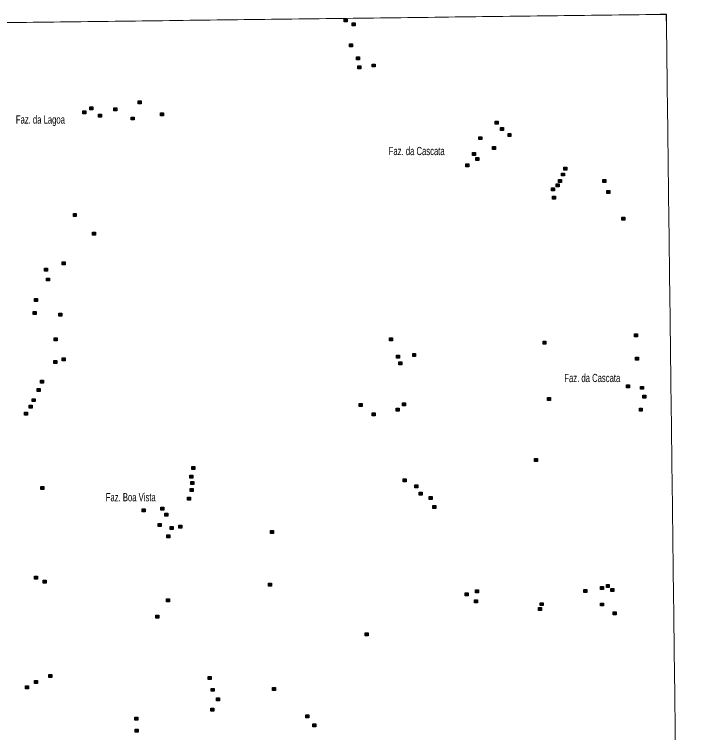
# Model space of a CAD drawing. Extents: x 265.7 to 292.1, y 7676.2 to 7704.2.
# Drawn here: x 285.4 to 292.1, y 7697.19 to 7704.2 of the extents above; entities that cross this region are included whole.
import ezdxf

# ---------------------------------------------------------------- set-up
doc = ezdxf.new("R2010")
doc.units = 0
doc.header["$LTSCALE"] = 0.032
doc.layers.add('2', color=7, linetype='Continuous', lineweight=25)
doc.layers.add('63', color=7, linetype='Continuous', lineweight=13)
doc.layers.add('61', color=7, linetype='Continuous')

msp = doc.modelspace()

# ---------------------------------------------------------------- hatches: boundary and pattern name
at = {"layer": '2'}
for points in [[(288.614, 7704.1576), (288.643, 7704.1576), (288.643, 7704.1286), (288.614, 7704.1286)], [(288.6907, 7704.1205), (288.7197, 7704.1205), (288.7197, 7704.0915), (288.6907, 7704.0915)], [(288.6656, 7703.9147), (288.6946, 7703.9147), (288.6946, 7703.8857), (288.6656, 7703.8857)], [(288.7334, 7703.7896), (288.7624, 7703.7896), (288.7624, 7703.7606), (288.7334, 7703.7606)], [(288.8868, 7703.7186), (288.9158, 7703.7186), (288.9158, 7703.6896), (288.8868, 7703.6896)], [(288.7478, 7703.6991), (288.7768, 7703.6991), (288.7768, 7703.6701), (288.7478, 7703.6701)], [(286.6037, 7703.3586), (286.6327, 7703.3586), (286.6327, 7703.3296), (286.6037, 7703.3296)], [(286.1315, 7703.2998), (286.1605, 7703.2998), (286.1605, 7703.2708), (286.1315, 7703.2708)], [(286.3647, 7703.2899), (286.3937, 7703.2899), (286.3937, 7703.2609), (286.3647, 7703.2609)], [(286.062, 7703.2617), (286.091, 7703.2617), (286.091, 7703.2327), (286.062, 7703.2327)], [(286.2178, 7703.2295), (286.2468, 7703.2295), (286.2468, 7703.2005), (286.2178, 7703.2005)], [(286.8207, 7703.2408), (286.8497, 7703.2408), (286.8497, 7703.2118), (286.8207, 7703.2118)], [(286.5342, 7703.2012), (286.5632, 7703.2012), (286.5632, 7703.1722), (286.5342, 7703.1722)], [(290.0861, 7703.16), (290.1151, 7703.16), (290.1151, 7703.131), (290.0861, 7703.131)], [(290.1385, 7703.0987), (290.1675, 7703.0987), (290.1675, 7703.0697), (290.1385, 7703.0697)], [(289.927, 7703.0092), (289.956, 7703.0092), (289.956, 7702.9802), (289.927, 7702.9802)], [(290.2127, 7703.0415), (290.2417, 7703.0415), (290.2417, 7703.0125), (290.2127, 7703.0125)], [(290.061, 7702.9131), (290.09, 7702.9131), (290.09, 7702.8841), (290.061, 7702.8841)], [(289.8657, 7702.855), (289.8947, 7702.855), (289.8947, 7702.826), (289.8657, 7702.826)], [(289.8997, 7702.8066), (289.9287, 7702.8066), (289.9287, 7702.7776), (289.8997, 7702.7776)], [(289.8018, 7702.7436), (289.8308, 7702.7436), (289.8308, 7702.7146), (289.8018, 7702.7146)], [(290.7357, 7702.6548), (290.7647, 7702.6548), (290.7647, 7702.6258), (290.7357, 7702.6258)], [(290.7563, 7702.7108), (290.7853, 7702.7108), (290.7853, 7702.6818), (290.7563, 7702.6818)], [(290.705, 7702.5919), (290.734, 7702.5919), (290.734, 7702.5629), (290.705, 7702.5629)], [(291.1393, 7702.5903), (291.1683, 7702.5903), (291.1683, 7702.5613), (291.1393, 7702.5613)], [(290.6364, 7702.5104), (290.6654, 7702.5104), (290.6654, 7702.4814), (290.6364, 7702.4814)], [(290.6825, 7702.5484), (290.7115, 7702.5484), (290.7115, 7702.5194), (290.6825, 7702.5194)], [(291.178, 7702.4838), (291.207, 7702.4838), (291.207, 7702.4548), (291.178, 7702.4548)], [(290.647, 7702.429), (290.676, 7702.429), (290.676, 7702.4), (290.647, 7702.4)], [(285.9709, 7702.2586), (285.9999, 7702.2586), (285.9999, 7702.2296), (285.9709, 7702.2296)], [(291.324, 7702.2223), (291.353, 7702.2223), (291.353, 7702.1933), (291.324, 7702.1933)], [(286.1565, 7702.0786), (286.1855, 7702.0786), (286.1855, 7702.0496), (286.1565, 7702.0496)], [(285.8612, 7701.7865), (285.8902, 7701.7865), (285.8902, 7701.7575), (285.8612, 7701.7575)], [(285.6884, 7701.7251), (285.7174, 7701.7251), (285.7174, 7701.6961), (285.6884, 7701.6961)], [(285.7101, 7701.6299), (285.7391, 7701.6299), (285.7391, 7701.6009), (285.7101, 7701.6009)], [(285.5932, 7701.4307), (285.6222, 7701.4307), (285.6222, 7701.4017), (285.5932, 7701.4017)], [(285.5796, 7701.3039), (285.6086, 7701.3039), (285.6086, 7701.2749), (285.5796, 7701.2749)], [(285.8295, 7701.2877), (285.8585, 7701.2877), (285.8585, 7701.2587), (285.8295, 7701.2587)], [(285.7837, 7701.0457), (285.8127, 7701.0457), (285.8127, 7701.0167), (285.7837, 7701.0167)], [(289.0554, 7701.0456), (289.0844, 7701.0456), (289.0844, 7701.0166), (289.0554, 7701.0166)], [(291.4467, 7701.0851), (291.4757, 7701.0851), (291.4757, 7701.0561), (291.4467, 7701.0561)], [(290.5541, 7701.0134), (290.5831, 7701.0134), (290.5831, 7700.9844), (290.5541, 7700.9844)], [(285.8612, 7700.8494), (285.8902, 7700.8494), (285.8902, 7700.8204), (285.8612, 7700.8204)], [(289.1231, 7700.8754), (289.1521, 7700.8754), (289.1521, 7700.8464), (289.1231, 7700.8464)], [(289.2824, 7700.893), (289.3114, 7700.893), (289.3114, 7700.864), (289.2824, 7700.864)], [(291.4564, 7700.8576), (291.4854, 7700.8576), (291.4854, 7700.8286), (291.4564, 7700.8286)], [(285.7803, 7700.8236), (285.8093, 7700.8236), (285.8093, 7700.7946), (285.7803, 7700.7946)], [(289.1459, 7700.8107), (289.1749, 7700.8107), (289.1749, 7700.7817), (289.1459, 7700.7817)], [(285.6497, 7700.6341), (285.6787, 7700.6341), (285.6787, 7700.6051), (285.6497, 7700.6051)], [(285.6174, 7700.5517), (285.6464, 7700.5517), (285.6464, 7700.5227), (285.6174, 7700.5227)], [(291.3685, 7700.5872), (291.3975, 7700.5872), (291.3975, 7700.5582), (291.3685, 7700.5582)], [(291.5064, 7700.5727), (291.5354, 7700.5727), (291.5354, 7700.5437), (291.5064, 7700.5437)], [(291.529, 7700.4871), (291.558, 7700.4871), (291.558, 7700.4581), (291.529, 7700.4581)], [(285.5697, 7700.4524), (285.5987, 7700.4524), (285.5987, 7700.4234), (285.5697, 7700.4234)], [(288.7593, 7700.4065), (288.7883, 7700.4065), (288.7883, 7700.3775), (288.7593, 7700.3775)], [(289.1822, 7700.412), (289.2112, 7700.412), (289.2112, 7700.383), (289.1822, 7700.383)], [(290.5993, 7700.463), (290.6283, 7700.463), (290.6283, 7700.434), (290.5993, 7700.434)], [(285.5391, 7700.388), (285.5681, 7700.388), (285.5681, 7700.359), (285.5391, 7700.359)], [(289.1216, 7700.3589), (289.1506, 7700.3589), (289.1506, 7700.3299), (289.1216, 7700.3299)], [(291.4944, 7700.3596), (291.5234, 7700.3596), (291.5234, 7700.3306), (291.4944, 7700.3306)], [(285.4939, 7700.32), (285.5229, 7700.32), (285.5229, 7700.291), (285.4939, 7700.291)], [(288.8876, 7700.3127), (288.9166, 7700.3127), (288.9166, 7700.2837), (288.8876, 7700.2837)], [(290.4718, 7699.8674), (290.5008, 7699.8674), (290.5008, 7699.8384), (290.4718, 7699.8384)], [(287.1266, 7699.7907), (287.1556, 7699.7907), (287.1556, 7699.7617), (287.1266, 7699.7617)], [(287.1088, 7699.7067), (287.1378, 7699.7067), (287.1378, 7699.6777), (287.1088, 7699.6777)], [(287.1168, 7699.6446), (287.1458, 7699.6446), (287.1458, 7699.6156), (287.1168, 7699.6156)], [(289.1894, 7699.6687), (289.2184, 7699.6687), (289.2184, 7699.6397), (289.1894, 7699.6397)], [(285.6529, 7699.5962), (285.6819, 7699.5962), (285.6819, 7699.5672), (285.6529, 7699.5672)], [(287.1113, 7699.5751), (287.1403, 7699.5751), (287.1403, 7699.5461), (287.1113, 7699.5461)], [(289.304, 7699.6107), (289.333, 7699.6107), (289.333, 7699.5817), (289.304, 7699.5817)], [(289.346, 7699.5413), (289.375, 7699.5413), (289.375, 7699.5123), (289.346, 7699.5123)], [(289.442, 7699.4976), (289.471, 7699.4976), (289.471, 7699.4686), (289.442, 7699.4686)], [(287.0845, 7699.4921), (287.1135, 7699.4921), (287.1135, 7699.4631), (287.0845, 7699.4631)], [(286.644, 7699.3783), (286.673, 7699.3783), (286.673, 7699.3493), (286.644, 7699.3493)], [(286.8256, 7699.3936), (286.8546, 7699.3936), (286.8546, 7699.3646), (286.8256, 7699.3646)], [(289.4791, 7699.4089), (289.5081, 7699.4089), (289.5081, 7699.3799), (289.4791, 7699.3799)], [(286.8643, 7699.3347), (286.8933, 7699.3347), (286.8933, 7699.3057), (286.8643, 7699.3057)], [(286.7989, 7699.2345), (286.8279, 7699.2345), (286.8279, 7699.2055), (286.7989, 7699.2055)], [(287.0006, 7699.2185), (287.0296, 7699.2185), (287.0296, 7699.1895), (287.0006, 7699.1895)], [(286.9167, 7699.204), (286.9457, 7699.204), (286.9457, 7699.175), (286.9167, 7699.175)], [(287.8964, 7699.166), (287.9254, 7699.166), (287.9254, 7699.137), (287.8964, 7699.137)], [(286.8828, 7699.1232), (286.9118, 7699.1232), (286.9118, 7699.0942), (286.8828, 7699.0942)], [(285.5924, 7698.7197), (285.6214, 7698.7197), (285.6214, 7698.6907), (285.5924, 7698.6907)], [(285.6763, 7698.6801), (285.7053, 7698.6801), (285.7053, 7698.6511), (285.6763, 7698.6511)], [(287.8764, 7698.6511), (287.9054, 7698.6511), (287.9054, 7698.6221), (287.8764, 7698.6221)], [(289.8948, 7698.5857), (289.9238, 7698.5857), (289.9238, 7698.5567), (289.8948, 7698.5567)], [(290.9536, 7698.5897), (290.9826, 7698.5897), (290.9826, 7698.5607), (290.9536, 7698.5607)], [(291.115, 7698.6187), (291.144, 7698.6187), (291.144, 7698.5897), (291.115, 7698.5897)], [(291.1723, 7698.639), (291.2013, 7698.639), (291.2013, 7698.61), (291.1723, 7698.61)], [(291.2168, 7698.5995), (291.2458, 7698.5995), (291.2458, 7698.5705), (291.2168, 7698.5705)], [(289.7947, 7698.5582), (289.8237, 7698.5582), (289.8237, 7698.5292), (289.7947, 7698.5292)], [(286.8812, 7698.4986), (286.9102, 7698.4986), (286.9102, 7698.4696), (286.8812, 7698.4696)], [(289.885, 7698.4889), (289.914, 7698.4889), (289.914, 7698.4599), (289.885, 7698.4599)], [(290.5275, 7698.4614), (290.5565, 7698.4614), (290.5565, 7698.4324), (290.5275, 7698.4324)], [(291.115, 7698.4582), (291.144, 7698.4582), (291.144, 7698.4292), (291.115, 7698.4292)], [(290.5098, 7698.4139), (290.5388, 7698.4139), (290.5388, 7698.3849), (290.5098, 7698.3849)], [(286.7755, 7698.3388), (286.8045, 7698.3388), (286.8045, 7698.3098), (286.7755, 7698.3098)], [(291.2401, 7698.3711), (291.2691, 7698.3711), (291.2691, 7698.3421), (291.2401, 7698.3421)], [(288.8173, 7698.1684), (288.8463, 7698.1684), (288.8463, 7698.1394), (288.8173, 7698.1394)], [(285.7321, 7697.7609), (285.7611, 7697.7609), (285.7611, 7697.7319), (285.7321, 7697.7319)], [(285.5931, 7697.7013), (285.6221, 7697.7013), (285.6221, 7697.6723), (285.5931, 7697.6723)], [(287.2856, 7697.7415), (287.3146, 7697.7415), (287.3146, 7697.7125), (287.2856, 7697.7125)], [(285.5044, 7697.6496), (285.5334, 7697.6496), (285.5334, 7697.6206), (285.5044, 7697.6206)], [(287.3146, 7697.6254), (287.3436, 7697.6254), (287.3436, 7697.5964), (287.3146, 7697.5964)], [(287.9158, 7697.635), (287.9448, 7697.635), (287.9448, 7697.606), (287.9158, 7697.606)], [(287.3678, 7697.5317), (287.3968, 7697.5317), (287.3968, 7697.5027), (287.3678, 7697.5027)], [(287.3139, 7697.4333), (287.3429, 7697.4333), (287.3429, 7697.4043), (287.3139, 7697.4043)], [(286.5706, 7697.3429), (286.5996, 7697.3429), (286.5996, 7697.3139), (286.5706, 7697.3139)], [(288.2411, 7697.3679), (288.2701, 7697.3679), (288.2701, 7697.3389), (288.2411, 7697.3389)], [(288.3073, 7697.2783), (288.3363, 7697.2783), (288.3363, 7697.2493), (288.3073, 7697.2493)], [(286.5737, 7697.2267), (286.6027, 7697.2267), (286.6027, 7697.1977), (286.5737, 7697.1977)]]:
    msp.add_hatch(color=256, dxfattribs=at).paths.add_polyline_path(points)

# ---------------------------------------------------------------- linework, layer by layer
for points in [[(288.614, 7704.1576), (288.643, 7704.1576), (288.643, 7704.1286), (288.614, 7704.1286)], [(288.6907, 7704.1205), (288.7197, 7704.1205), (288.7197, 7704.0915), (288.6907, 7704.0915)], [(288.6656, 7703.9147), (288.6946, 7703.9147), (288.6946, 7703.8857), (288.6656, 7703.8857)], [(288.7334, 7703.7896), (288.7624, 7703.7896), (288.7624, 7703.7606), (288.7334, 7703.7606)], [(288.8868, 7703.7186), (288.9158, 7703.7186), (288.9158, 7703.6896), (288.8868, 7703.6896)], [(288.7478, 7703.6991), (288.7768, 7703.6991), (288.7768, 7703.6701), (288.7478, 7703.6701)], [(286.6037, 7703.3586), (286.6327, 7703.3586), (286.6327, 7703.3296), (286.6037, 7703.3296)], [(286.1315, 7703.2998), (286.1605, 7703.2998), (286.1605, 7703.2708), (286.1315, 7703.2708)], [(286.3647, 7703.2899), (286.3937, 7703.2899), (286.3937, 7703.2609), (286.3647, 7703.2609)], [(286.062, 7703.2617), (286.091, 7703.2617), (286.091, 7703.2327), (286.062, 7703.2327)], [(286.2178, 7703.2295), (286.2468, 7703.2295), (286.2468, 7703.2005), (286.2178, 7703.2005)], [(286.8207, 7703.2408), (286.8497, 7703.2408), (286.8497, 7703.2118), (286.8207, 7703.2118)], [(286.5342, 7703.2012), (286.5632, 7703.2012), (286.5632, 7703.1722), (286.5342, 7703.1722)], [(290.0861, 7703.16), (290.1151, 7703.16), (290.1151, 7703.131), (290.0861, 7703.131)], [(290.1385, 7703.0987), (290.1675, 7703.0987), (290.1675, 7703.0697), (290.1385, 7703.0697)], [(289.927, 7703.0092), (289.956, 7703.0092), (289.956, 7702.9802), (289.927, 7702.9802)], [(290.2127, 7703.0415), (290.2417, 7703.0415), (290.2417, 7703.0125), (290.2127, 7703.0125)], [(290.061, 7702.9131), (290.09, 7702.9131), (290.09, 7702.8841), (290.061, 7702.8841)], [(289.8657, 7702.855), (289.8947, 7702.855), (289.8947, 7702.826), (289.8657, 7702.826)], [(289.8997, 7702.8066), (289.9287, 7702.8066), (289.9287, 7702.7776), (289.8997, 7702.7776)], [(289.8018, 7702.7436), (289.8308, 7702.7436), (289.8308, 7702.7146), (289.8018, 7702.7146)], [(290.7357, 7702.6548), (290.7647, 7702.6548), (290.7647, 7702.6258), (290.7357, 7702.6258)], [(290.7563, 7702.7108), (290.7853, 7702.7108), (290.7853, 7702.6818), (290.7563, 7702.6818)], [(290.705, 7702.5919), (290.734, 7702.5919), (290.734, 7702.5629), (290.705, 7702.5629)], [(291.1393, 7702.5903), (291.1683, 7702.5903), (291.1683, 7702.5613), (291.1393, 7702.5613)], [(290.6364, 7702.5104), (290.6654, 7702.5104), (290.6654, 7702.4814), (290.6364, 7702.4814)], [(290.6825, 7702.5484), (290.7115, 7702.5484), (290.7115, 7702.5194), (290.6825, 7702.5194)], [(291.178, 7702.4838), (291.207, 7702.4838), (291.207, 7702.4548), (291.178, 7702.4548)], [(290.647, 7702.429), (290.676, 7702.429), (290.676, 7702.4), (290.647, 7702.4)], [(285.9709, 7702.2586), (285.9999, 7702.2586), (285.9999, 7702.2296), (285.9709, 7702.2296)], [(291.324, 7702.2223), (291.353, 7702.2223), (291.353, 7702.1933), (291.324, 7702.1933)], [(286.1565, 7702.0786), (286.1855, 7702.0786), (286.1855, 7702.0496), (286.1565, 7702.0496)], [(285.8612, 7701.7865), (285.8902, 7701.7865), (285.8902, 7701.7575), (285.8612, 7701.7575)], [(285.6884, 7701.7251), (285.7174, 7701.7251), (285.7174, 7701.6961), (285.6884, 7701.6961)], [(285.7101, 7701.6299), (285.7391, 7701.6299), (285.7391, 7701.6009), (285.7101, 7701.6009)], [(285.5932, 7701.4307), (285.6222, 7701.4307), (285.6222, 7701.4017), (285.5932, 7701.4017)], [(285.5796, 7701.3039), (285.6086, 7701.3039), (285.6086, 7701.2749), (285.5796, 7701.2749)], [(285.8295, 7701.2877), (285.8585, 7701.2877), (285.8585, 7701.2587), (285.8295, 7701.2587)], [(285.7837, 7701.0457), (285.8127, 7701.0457), (285.8127, 7701.0167), (285.7837, 7701.0167)], [(289.0554, 7701.0456), (289.0844, 7701.0456), (289.0844, 7701.0166), (289.0554, 7701.0166)], [(291.4467, 7701.0851), (291.4757, 7701.0851), (291.4757, 7701.0561), (291.4467, 7701.0561)], [(290.5541, 7701.0134), (290.5831, 7701.0134), (290.5831, 7700.9844), (290.5541, 7700.9844)], [(285.8612, 7700.8494), (285.8902, 7700.8494), (285.8902, 7700.8204), (285.8612, 7700.8204)], [(289.1231, 7700.8754), (289.1521, 7700.8754), (289.1521, 7700.8464), (289.1231, 7700.8464)], [(289.2824, 7700.893), (289.3114, 7700.893), (289.3114, 7700.864), (289.2824, 7700.864)], [(291.4564, 7700.8576), (291.4854, 7700.8576), (291.4854, 7700.8286), (291.4564, 7700.8286)], [(285.7803, 7700.8236), (285.8093, 7700.8236), (285.8093, 7700.7946), (285.7803, 7700.7946)], [(289.1459, 7700.8107), (289.1749, 7700.8107), (289.1749, 7700.7817), (289.1459, 7700.7817)], [(285.6497, 7700.6341), (285.6787, 7700.6341), (285.6787, 7700.6051), (285.6497, 7700.6051)], [(285.6174, 7700.5517), (285.6464, 7700.5517), (285.6464, 7700.5227), (285.6174, 7700.5227)], [(291.3685, 7700.5872), (291.3975, 7700.5872), (291.3975, 7700.5582), (291.3685, 7700.5582)], [(291.5064, 7700.5727), (291.5354, 7700.5727), (291.5354, 7700.5437), (291.5064, 7700.5437)], [(291.529, 7700.4871), (291.558, 7700.4871), (291.558, 7700.4581), (291.529, 7700.4581)], [(285.5697, 7700.4524), (285.5987, 7700.4524), (285.5987, 7700.4234), (285.5697, 7700.4234)], [(288.7593, 7700.4065), (288.7883, 7700.4065), (288.7883, 7700.3775), (288.7593, 7700.3775)], [(289.1822, 7700.412), (289.2112, 7700.412), (289.2112, 7700.383), (289.1822, 7700.383)], [(290.5993, 7700.463), (290.6283, 7700.463), (290.6283, 7700.434), (290.5993, 7700.434)], [(285.5391, 7700.388), (285.5681, 7700.388), (285.5681, 7700.359), (285.5391, 7700.359)], [(289.1216, 7700.3589), (289.1506, 7700.3589), (289.1506, 7700.3299), (289.1216, 7700.3299)], [(291.4944, 7700.3596), (291.5234, 7700.3596), (291.5234, 7700.3306), (291.4944, 7700.3306)], [(285.4939, 7700.32), (285.5229, 7700.32), (285.5229, 7700.291), (285.4939, 7700.291)], [(288.8876, 7700.3127), (288.9166, 7700.3127), (288.9166, 7700.2837), (288.8876, 7700.2837)], [(290.4718, 7699.8674), (290.5008, 7699.8674), (290.5008, 7699.8384), (290.4718, 7699.8384)], [(287.1266, 7699.7907), (287.1556, 7699.7907), (287.1556, 7699.7617), (287.1266, 7699.7617)], [(287.1088, 7699.7067), (287.1378, 7699.7067), (287.1378, 7699.6777), (287.1088, 7699.6777)], [(287.1168, 7699.6446), (287.1458, 7699.6446), (287.1458, 7699.6156), (287.1168, 7699.6156)], [(289.1894, 7699.6687), (289.2184, 7699.6687), (289.2184, 7699.6397), (289.1894, 7699.6397)], [(285.6529, 7699.5962), (285.6819, 7699.5962), (285.6819, 7699.5672), (285.6529, 7699.5672)], [(287.1113, 7699.5751), (287.1403, 7699.5751), (287.1403, 7699.5461), (287.1113, 7699.5461)], [(289.304, 7699.6107), (289.333, 7699.6107), (289.333, 7699.5817), (289.304, 7699.5817)], [(289.346, 7699.5413), (289.375, 7699.5413), (289.375, 7699.5123), (289.346, 7699.5123)], [(289.442, 7699.4976), (289.471, 7699.4976), (289.471, 7699.4686), (289.442, 7699.4686)], [(287.0845, 7699.4921), (287.1135, 7699.4921), (287.1135, 7699.4631), (287.0845, 7699.4631)], [(286.644, 7699.3783), (286.673, 7699.3783), (286.673, 7699.3493), (286.644, 7699.3493)], [(286.8256, 7699.3936), (286.8546, 7699.3936), (286.8546, 7699.3646), (286.8256, 7699.3646)], [(289.4791, 7699.4089), (289.5081, 7699.4089), (289.5081, 7699.3799), (289.4791, 7699.3799)], [(286.8643, 7699.3347), (286.8933, 7699.3347), (286.8933, 7699.3057), (286.8643, 7699.3057)], [(286.7989, 7699.2345), (286.8279, 7699.2345), (286.8279, 7699.2055), (286.7989, 7699.2055)], [(287.0006, 7699.2185), (287.0296, 7699.2185), (287.0296, 7699.1895), (287.0006, 7699.1895)], [(286.9167, 7699.204), (286.9457, 7699.204), (286.9457, 7699.175), (286.9167, 7699.175)], [(287.8964, 7699.166), (287.9254, 7699.166), (287.9254, 7699.137), (287.8964, 7699.137)], [(286.8828, 7699.1232), (286.9118, 7699.1232), (286.9118, 7699.0942), (286.8828, 7699.0942)], [(285.5924, 7698.7197), (285.6214, 7698.7197), (285.6214, 7698.6907), (285.5924, 7698.6907)], [(285.6763, 7698.6801), (285.7053, 7698.6801), (285.7053, 7698.6511), (285.6763, 7698.6511)], [(287.8764, 7698.6511), (287.9054, 7698.6511), (287.9054, 7698.6221), (287.8764, 7698.6221)], [(289.8948, 7698.5857), (289.9238, 7698.5857), (289.9238, 7698.5567), (289.8948, 7698.5567)], [(290.9536, 7698.5897), (290.9826, 7698.5897), (290.9826, 7698.5607), (290.9536, 7698.5607)], [(291.115, 7698.6187), (291.144, 7698.6187), (291.144, 7698.5897), (291.115, 7698.5897)], [(291.1723, 7698.639), (291.2013, 7698.639), (291.2013, 7698.61), (291.1723, 7698.61)], [(291.2168, 7698.5995), (291.2458, 7698.5995), (291.2458, 7698.5705), (291.2168, 7698.5705)], [(289.7947, 7698.5582), (289.8237, 7698.5582), (289.8237, 7698.5292), (289.7947, 7698.5292)], [(286.8812, 7698.4986), (286.9102, 7698.4986), (286.9102, 7698.4696), (286.8812, 7698.4696)], [(289.885, 7698.4889), (289.914, 7698.4889), (289.914, 7698.4599), (289.885, 7698.4599)], [(290.5275, 7698.4614), (290.5565, 7698.4614), (290.5565, 7698.4324), (290.5275, 7698.4324)], [(291.115, 7698.4582), (291.144, 7698.4582), (291.144, 7698.4292), (291.115, 7698.4292)], [(290.5098, 7698.4139), (290.5388, 7698.4139), (290.5388, 7698.3849), (290.5098, 7698.3849)], [(286.7755, 7698.3388), (286.8045, 7698.3388), (286.8045, 7698.3098), (286.7755, 7698.3098)], [(291.2401, 7698.3711), (291.2691, 7698.3711), (291.2691, 7698.3421), (291.2401, 7698.3421)], [(288.8173, 7698.1684), (288.8463, 7698.1684), (288.8463, 7698.1394), (288.8173, 7698.1394)], [(285.7321, 7697.7609), (285.7611, 7697.7609), (285.7611, 7697.7319), (285.7321, 7697.7319)], [(285.5931, 7697.7013), (285.6221, 7697.7013), (285.6221, 7697.6723), (285.5931, 7697.6723)], [(287.2856, 7697.7415), (287.3146, 7697.7415), (287.3146, 7697.7125), (287.2856, 7697.7125)], [(285.5044, 7697.6496), (285.5334, 7697.6496), (285.5334, 7697.6206), (285.5044, 7697.6206)], [(287.3146, 7697.6254), (287.3436, 7697.6254), (287.3436, 7697.5964), (287.3146, 7697.5964)], [(287.9158, 7697.635), (287.9448, 7697.635), (287.9448, 7697.606), (287.9158, 7697.606)], [(287.3678, 7697.5317), (287.3968, 7697.5317), (287.3968, 7697.5027), (287.3678, 7697.5027)], [(287.3139, 7697.4333), (287.3429, 7697.4333), (287.3429, 7697.4043), (287.3139, 7697.4043)], [(286.5706, 7697.3429), (286.5996, 7697.3429), (286.5996, 7697.3139), (286.5706, 7697.3139)], [(288.2411, 7697.3679), (288.2701, 7697.3679), (288.2701, 7697.3389), (288.2411, 7697.3389)], [(288.3073, 7697.2783), (288.3363, 7697.2783), (288.3363, 7697.2493), (288.3073, 7697.2493)], [(286.5737, 7697.2267), (286.6027, 7697.2267), (286.6027, 7697.1977), (286.5737, 7697.1977)]]:
    msp.add_lwpolyline(points, close=True, dxfattribs=at)
at = {"layer": '63', "lineweight": 25}
msp.add_lwpolyline([(291.7584, 7704.1407), (291.7584, 7704.2023), (291.6977, 7704.2023)], dxfattribs=at)
at = {"layer": '63'}
for points in [[(265.7179, 7703.8606), (266.2494, 7703.868), (266.7808, 7703.8754), (267.3123, 7703.8828), (267.8437, 7703.8901), (268.3752, 7703.8974), (268.9066, 7703.9047), (269.4381, 7703.912), (269.9695, 7703.9193), (270.501, 7703.9265), (271.0324, 7703.9338), (271.5639, 7703.941), (272.0953, 7703.9482), (272.6268, 7703.9554), (273.1582, 7703.9626), (273.6896, 7703.9697), (274.2211, 7703.9769), (274.7525, 7703.984), (275.2839, 7703.9911), (275.8154, 7703.9982), (276.3468, 7704.0052), (276.8782, 7704.0123), (277.4097, 7704.0193), (277.9411, 7704.0263), (278.4725, 7704.0333), (279.0039, 7704.0403), (279.5354, 7704.0473), (280.0668, 7704.0543), (280.5982, 7704.0612), (281.1296, 7704.0681), (281.661, 7704.075), (282.1925, 7704.0819), (282.7239, 7704.0888), (283.2553, 7704.0956), (283.7867, 7704.1025), (284.3181, 7704.1093), (284.8495, 7704.1161), (285.3809, 7704.1229), (285.9123, 7704.1296), (286.4437, 7704.1364), (286.9751, 7704.1431), (287.5065, 7704.1498), (288.0379, 7704.1565), (288.5693, 7704.1632), (289.1007, 7704.1699), (289.6321, 7704.1765), (290.1635, 7704.1832), (290.6949, 7704.1898), (291.2263, 7704.1964), (291.7577, 7704.203)], [(292.1022, 7676.5221), (292.0951, 7677.087), (292.088, 7677.6519), (292.081, 7678.2168), (292.0739, 7678.7818), (292.0668, 7679.3467), (292.0598, 7679.9116), (292.0527, 7680.4765), (292.0457, 7681.0414), (292.0386, 7681.6064), (292.0316, 7682.1713), (292.0245, 7682.7362), (292.0175, 7683.3011), (292.0104, 7683.866), (292.0034, 7684.431), (291.9963, 7684.9959), (291.9893, 7685.5608), (291.9822, 7686.1257), (291.9752, 7686.6906), (291.9681, 7687.2556), (291.9611, 7687.8205), (291.9541, 7688.3854), (291.947, 7688.9503), (291.94, 7689.5152), (291.933, 7690.0801), (291.9259, 7690.6451), (291.9189, 7691.21), (291.9119, 7691.7749), (291.9049, 7692.3398), (291.8978, 7692.9047), (291.8908, 7693.4696), (291.8838, 7694.0345), (291.8768, 7694.5995), (291.8698, 7695.1644), (291.8628, 7695.7293), (291.8557, 7696.2942), (291.8487, 7696.8591), (291.8417, 7697.424), (291.8347, 7697.9889), (291.8277, 7698.5539), (291.8207, 7699.1188), (291.8137, 7699.6837), (291.8067, 7700.2486), (291.7997, 7700.8135), (291.7927, 7701.3784), (291.7857, 7701.9433), (291.7787, 7702.5082), (291.7717, 7703.0731), (291.7647, 7703.638), (291.7577, 7704.203)]]:
    msp.add_spline(points, degree=3, dxfattribs=at)

# ---------------------------------------------------------------- texts
at = {"layer": '61', "width": 0.7}
for s, p in [('Faz. da Lagoa', (285.4098, 7703.1366)), ('Faz. da Cascata', (289.0489, 7702.8294)), ('Faz. da Cascata', (290.7627, 7700.6143)), ('Faz. Boa Vista', (286.2874, 7699.4503))]:
    msp.add_text(s, height=0.08, dxfattribs=at).set_placement(p)

doc.saveas('drawing.dxf')
